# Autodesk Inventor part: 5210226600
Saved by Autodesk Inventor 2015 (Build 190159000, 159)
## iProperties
Created: 2020-07
Part Number: 5210226600
Checked By: TraceParts S.A.
Material: Generic
Catalog Web Link: www.traceparts.com
Document SubType Name: Modeling
Designer: TraceParts
Density: 1 g/cm^3
Appearance: Default
Company: TraceParts S.A.
Author: TraceParts
REFERENCE: 5210226600
DESIGN: TDM-300 (230V 50) RE - 5210226600
SUPPLIER: Soler & Palau
TraceParts.PartNumber: 10-20122018-119657
TraceParts.PartTitle: TDM
TraceParts.InstanceId: 10-20122018-1196571ESI8RSJZ8RDJ4QLCUPOQZ6UL
TraceParts.PartStatus: Published
TraceParts.PartVersion: 1.0.2
TRACEPARTS: TRACEPARTS
TraceParts.PartLanguage: en
TraceParts.ClassPath: SOLER_PALAU:10-20122018-119657
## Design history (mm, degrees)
feature "5210226600"
body "Solid1"
